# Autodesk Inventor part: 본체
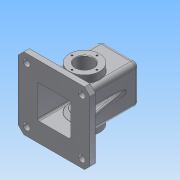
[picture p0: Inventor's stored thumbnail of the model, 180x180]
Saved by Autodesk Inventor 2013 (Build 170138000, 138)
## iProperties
Created: 2016-02
Part Number: 본체
Material: 알루미늄 6061
Document SubType Name: Modeling
Designer: Administrator
Density: 2.71 g/cm^3
Mass: 934.459 g
Surface Area: 1040.12 cm^2
Volume: 344.819 cm^3
Author: Administrator
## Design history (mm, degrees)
sketch "스케치1"
  geometry: L1 (-35, -35)-(35, -35); L2 (35, -35)-(35, 35); L3 (35, 35)-(-35, 35); L4 (-35, 35)-(-35, -35); L5 (-35, -35)-(35, 35); L6 (35, -35)-(-35, 35); 1 further point
  constraints: 12 end point, 2 midpoint, 2 parallel, 2 perpendicular, 1 horizontal
  dimensions: "d0" = 70 distance of L2.end L3.end
extrude "돌출1" new body sketch "스케치1" distance "d2" = 120; taper "d3" = 0 deg
fillet "모깎기1" dims "d5" = 8
fillet "모깎기2" dims "d6" = 8
feature "쉘1" dims "d7" = 5
sketch "스케치2"
  geometry: L1 (-65, -65)-(65, -65); L2 (65, -65)-(65, 65); L3 (65, 65)-(-65, 65); L4 (-65, 65)-(-65, -65); L5 (-65, -65)-(65, 65); L6 (65, -65)-(-65, 65); L7 (30, -27)-(30, 27) reference; L8 (27, 30)-(-27, 30) reference; L9 (-30, 27)-(-30, -27) reference; L10 (-27, -30)-(27, -30) reference; L11 (27, -35)-(-27, -35) reference; L12 (-35, -27)-(-35, 27) reference; L13 (-27, 35)-(27, 35) reference; L14 (35, 27)-(35, -27) reference; A1 r 3 centre (27, -27) between (27, -30) and (30, -27) reference; A2 r 3 centre (27, 27) between (30, 27) and (27, 30) reference; A3 r 3 centre (-27, 27) between (-27, 30) and (-30, 27) reference; A4 r 3 centre (-27, -27) between (-30, -27) and (-27, -30) reference; A5 r 8 centre (27, -27) between (27, -35) and (35, -27) reference; A6 r 8 centre (-27, -27) between (-35, -27) and (-27, -35) reference; A7 r 8 centre (-27, 27) between (-27, 35) and (-35, 27) reference; A8 r 8 centre (27, 27) between (35, 27) and (27, 35) reference; 1 further point
  constraints: 12 end point, 2 midpoint, 2 parallel, 2 perpendicular, 1 horizontal
  dimensions: "d8" = 130 distance of L2.end L3.end
extrude "돌출2" join sketch "스케치2" distance "d10" = 10; taper "d11" = 0 deg
sketch "스케치3"
  geometry: L1 (65, 65)-(-65, 65) reference; L2 (65, -65)-(65, 65) reference; 3 further points
  constraints: 1 vertical alignment
  dimensions: "d12" = 100 distance of point (50, 50) point (50, -50); "d14" = 15 distance from line of L1 point (50, 50); "d15" = 15 distance from line of point (50, 50) L2
hole "구멍1" sketch "스케치3" at (50, -50), (50, 50) diameter "d16" = 12; stored, may be unused: countersink angle "d20" = 90 deg, drill point angle "d22" = 0 deg; dims "d17" = 6, "d18" = 4, "d19" = 2, "d21" = 8
chamfer "모따기1" distance "d23" = 10; stored, may be unused: second distance "d24" = 2, angle "d25" = 45 deg
node "작업 평면1"
sketch "스케치5"
  geometry: L1 (-27, 0)-(27, 0) reference; C1 r 27.5 at (0, 55); 1 further point
  constraints: 1 centre point, 1 midpoint, 1 vertical alignment
  dimensions: "d26" = 55 diameter of C1; "d29" = 55 distance of point (0, 0) C1.centre
extrude "돌출3" join sketch "스케치5" stored distance "d30" = 10; taper "d31" = 0 deg
sketch "스케치6"
  geometry: C1 r 27.5 at (27, 55) reference; C2 r 27.5 at (27, 55); 1 further point
  constraints: 1 centre point, 1 coincident
  dimensions: "d32" = 55 diameter of C2
extrude "돌출4" join sketch "스케치6" distance "d33" = 7; taper "d34" = -45 deg
hole "구멍2" diameter "d37" = 32; stored, may be unused: countersink angle "d41" = 90 deg, drill point angle "d43" = 0 deg; dims "d35" = 10, "d36" = 10, "d38" = 6, "d39" = 4, "d40" = 2, "d42" = 8
sketch "스케치7"
  geometry: C1 r 16 at (0, 0) reference; 2 further points
  constraints: 1 vertical alignment
  dimensions: "d44" = 22.5 distance of C1.centre point (0, 22.5)
hole "구멍3" sketch "스케치7" at (0, 22.5) diameter "d45" = 3.242; stored, may be unused: countersink angle "d49" = 90 deg, drill point angle "d51" = 118 deg; dims "d46" = 8, "d47" = 4, "d48" = 2, "d50" = 10
sketch "스케치8"
  geometry: C1 r 20 at (0, 0); 1 further point
  constraints: 1 centre point, 1 coincident
  dimensions: "d56" = 40 diameter of C1
extrude "돌출5" join sketch "스케치8" distance "d57" = 10; taper "d58" = -10 deg
hole "구멍4" diameter "d61" = 21; stored, may be unused: countersink angle "d65" = 90 deg, drill point angle "d67" = 0 deg; dims "d59" = 10, "d60" = 10, "d62" = 8, "d63" = 28, "d64" = 4, "d66" = 10
chamfer "모따기2" distance "d68" = 1; stored, may be unused: second distance "d69" = 2, angle "d70" = 45 deg
sketch "스케치9"
  geometry: L1 (27, 115)-(10.5, 115) reference; L2 (10.5, 115)-(10.5, 126) reference; L3 (10.5, 126)-(14, 126) reference; L4 (14, 126)-(14, 130) reference; L5 (14, 130)-(18.237, 130) reference; L6 (18.237, 130)-(20, 120) reference; L7 (20, 120)-(27, 120) reference; L8 (35, 112)-(35, 10) reference; L9 (35, 10)-(65, 10) reference; L10 (65, 10)-(65, 0) reference; L11 (65, 0)-(30, 0) reference; L12 (30, 0)-(30, 112) reference; L13 (-27, 120)-(-20, 120) reference; L14 (-20, 120)-(-18.237, 130) reference; L15 (-18.237, 130)-(-14, 130) reference; L16 (-14, 130)-(-14, 126) reference; L17 (-14, 126)-(-10.5, 126) reference; L18 (-10.5, 126)-(-10.5, 115) reference; L19 (-10.5, 115)-(-27, 115) reference; L20 (-30, 112)-(-30, 0) reference; L21 (-30, 0)-(-65, 0) reference; L22 (-65, 0)-(-65, 10) reference; L23 (-65, 10)-(-35, 10) reference; L24 (-35, 10)-(-35, 112) reference; L25 (35, 95.069)-(50, 10); A1 r 3 centre (27, 112) between (30, 112) and (27, 115) reference; A2 r 8 centre (27, 112) between (35, 112) and (27, 120) reference; A3 r 8 centre (-27, 112) between (-27, 120) and (-35, 112) reference; A4 r 3 centre (-27, 112) between (-27, 115) and (-30, 112) reference; 1 further point
  constraints: 2 end point, 1 midpoint, 1 point on line
  dimensions: "d71" = 10 deg angle of L10 L25; "d72" = 15 distance from line of L10 L25.end
feature "리브1" sketch "스케치9" dims "d73" = 1, "d74" = 10, "d75" = 0, "d76" = 0, "d77" = 1, "d78" = 1
sketch "스케치10"
  geometry: L1 (8.763, 18)-(45.237, 18) reference; A1 r 27.5 centre (27, -57) between (54, -51.78) and (0, -51.78) reference; 2 further points
  constraints: 1 vertical alignment, 1 other
  dimensions: "d79" = 30 distance from line of point (27, -12) L1
feature "엠보싱1" sketch "스케치10" dims "d0" = 70, "d80" = 0.5, "d81" = 0
fillet "모깎기3" dims "d82" = 0.5, "d83" = 3
fillet "모깎기5" dims "d85" = 3
fillet "모깎기6" dims "d86" = 3
fillet "모깎기7" dims "d87" = 3
node "솔리드1"
mirror "대칭1"
pattern_circular "원형 패턴1" dims angle "d53" = 360 deg
mirror "대칭2"
mirror "대칭3"
node "투영된 루프1"
node "절단 모서리 투영1"
node "절단 모서리 투영2"
other parameters: "d28" = 48
